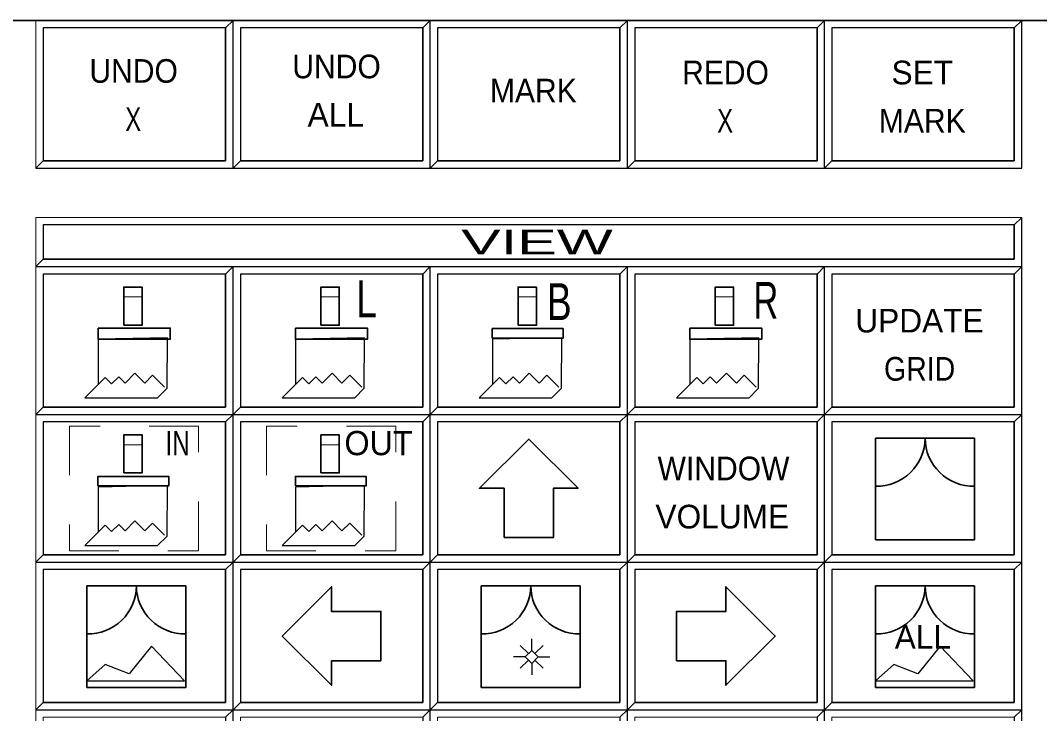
# Model space of a CAD drawing. Extents: x 95906.8 to 95923.6, y 90964.8 to 90972.8.
# Drawn here: x 95912.601 to 95914.669, y 90971.354 to 90972.762 of the extents above; entities that cross this region are included whole.
import ezdxf
from ezdxf.enums import TextEntityAlignment as Align

# ---------------------------------------------------------------- set-up
doc = ezdxf.new("R2010")
doc.units = 0
doc.header["$LTSCALE"] = 0.019
doc.linetypes.add('DOTTED', pattern=[1.5, 0.3, -1.2])
doc.linetypes.add('MEDIUM_DASHED', pattern=[4.5, 3, -1.5])
for name, color, linetype, lineweight in [('11', 7, 'Continuous', 25), ('12', 7, 'Continuous', 25), ('2', 7, 'Continuous', 13), ('21', 7, 'Continuous', 25), ('3', 7, 'Continuous', 25), ('6', 7, 'Continuous', 25), ('7', 7, 'Continuous', 35)]:
    doc.layers.add(name, color=color, linetype=linetype, lineweight=lineweight)

msp = doc.modelspace()

# ---------------------------------------------------------------- linework, layer by layer
at = {"layer": '11'}
for points in [[(95912.6473, 90972.4767), (95913.0173, 90972.4767), (95913.0173, 90972.7467), (95912.6473, 90972.7467)], [(95913.0473, 90972.4767), (95913.4173, 90972.4767), (95913.4173, 90972.7467), (95913.0473, 90972.7467)], [(95913.4473, 90972.4767), (95913.8173, 90972.4767), (95913.8173, 90972.7467), (95913.4473, 90972.7467)], [(95913.8473, 90972.4767), (95914.2173, 90972.4767), (95914.2173, 90972.7467), (95913.8473, 90972.7467)], [(95914.2473, 90972.4767), (95914.6173, 90972.4767), (95914.6173, 90972.7467), (95914.2473, 90972.7467)], [(95914.2473, 90971.9767), (95914.6173, 90971.9767), (95914.6173, 90972.2467), (95914.2473, 90972.2467)], [(95913.4473, 90971.6767), (95913.8173, 90971.6767), (95913.8173, 90971.9467), (95913.4473, 90971.9467)], [(95913.8473, 90971.6767), (95914.2173, 90971.6767), (95914.2173, 90971.9467), (95913.8473, 90971.9467)], [(95912.6473, 90971.3767), (95913.0173, 90971.3767), (95913.0173, 90971.6467), (95912.6473, 90971.6467)], [(95913.0473, 90971.3767), (95913.4173, 90971.3767), (95913.4173, 90971.6467), (95913.0473, 90971.6467)], [(95913.4473, 90971.3767), (95913.8173, 90971.3767), (95913.8173, 90971.6467), (95913.4473, 90971.6467)], [(95913.8473, 90971.3767), (95914.2173, 90971.3767), (95914.2173, 90971.6467), (95913.8473, 90971.6467)], [(95914.2473, 90971.3767), (95914.6173, 90971.3767), (95914.6173, 90971.6467), (95914.2473, 90971.6467)]]:
    msp.add_lwpolyline(points, close=True, dxfattribs=at)
at = {"layer": '12'}
for points in [[(95912.6473, 90971.9767), (95913.0173, 90971.9767), (95913.0173, 90972.2467), (95912.6473, 90972.2467)], [(95913.0473, 90971.9767), (95913.4173, 90971.9767), (95913.4173, 90972.2467), (95913.0473, 90972.2467)], [(95913.4473, 90971.9767), (95913.8173, 90971.9767), (95913.8173, 90972.2467), (95913.4473, 90972.2467)], [(95913.8473, 90971.9767), (95914.2173, 90971.9767), (95914.2173, 90972.2467), (95913.8473, 90972.2467)], [(95912.6473, 90971.6767), (95913.0173, 90971.6767), (95913.0173, 90971.9467), (95912.6473, 90971.9467)], [(95913.0473, 90971.6767), (95913.4173, 90971.6767), (95913.4173, 90971.9467), (95913.0473, 90971.9467)], [(95914.2473, 90971.6767), (95914.6173, 90971.6767), (95914.6173, 90971.9467), (95914.2473, 90971.9467)]]:
    msp.add_lwpolyline(points, close=True, dxfattribs=at)
at = {"layer": '2'}
for points in [[(95912.6323, 90972.7617), (95912.6323, 90972.4617), (95912.6473, 90972.4767), (95912.6473, 90972.7467), (95913.0173, 90972.7467), (95913.0323, 90972.7617)], [(95913.0323, 90972.7617), (95913.0323, 90972.4617), (95913.0473, 90972.4767), (95913.0473, 90972.7467), (95913.4173, 90972.7467), (95913.4323, 90972.7617)], [(95913.4323, 90972.7617), (95913.4323, 90972.4617), (95913.4473, 90972.4767), (95913.4473, 90972.7467), (95913.8173, 90972.7467), (95913.8323, 90972.7617)], [(95913.8323, 90972.7617), (95913.8323, 90972.4617), (95913.8473, 90972.4767), (95913.8473, 90972.7467), (95914.2173, 90972.7467), (95914.2323, 90972.7617)], [(95914.2323, 90972.7617), (95914.2323, 90972.4617), (95914.2473, 90972.4767), (95914.2473, 90972.7467), (95914.6173, 90972.7467), (95914.6323, 90972.7617)], [(95912.6323, 90972.3617), (95912.6323, 90972.2617), (95912.6473, 90972.2767), (95912.6473, 90972.3467), (95914.6173, 90972.3467), (95914.6323, 90972.3617)], [(95912.6323, 90972.2617), (95912.6323, 90971.9617), (95912.6473, 90971.9767), (95912.6473, 90972.2467), (95913.0173, 90972.2467), (95913.0323, 90972.2617)], [(95913.0323, 90972.2617), (95913.0323, 90971.9617), (95913.0473, 90971.9767), (95913.0473, 90972.2467), (95913.4173, 90972.2467), (95913.4323, 90972.2617)], [(95913.4323, 90972.2617), (95913.4323, 90971.9617), (95913.4473, 90971.9767), (95913.4473, 90972.2467), (95913.8173, 90972.2467), (95913.8323, 90972.2617)], [(95913.8323, 90972.2617), (95913.8323, 90971.9617), (95913.8473, 90971.9767), (95913.8473, 90972.2467), (95914.2173, 90972.2467), (95914.2323, 90972.2617)], [(95914.2323, 90972.2617), (95914.2323, 90971.9617), (95914.2473, 90971.9767), (95914.2473, 90972.2467), (95914.6173, 90972.2467), (95914.6323, 90972.2617)], [(95912.6323, 90971.9617), (95912.6323, 90971.6617), (95912.6473, 90971.6767), (95912.6473, 90971.9467), (95913.0173, 90971.9467), (95913.0323, 90971.9617)], [(95913.0323, 90971.9617), (95913.0323, 90971.6617), (95913.0473, 90971.6767), (95913.0473, 90971.9467), (95913.4173, 90971.9467), (95913.4323, 90971.9617)], [(95913.4323, 90971.9617), (95913.4323, 90971.6617), (95913.4473, 90971.6767), (95913.4473, 90971.9467), (95913.8173, 90971.9467), (95913.8323, 90971.9617)], [(95913.8323, 90971.9617), (95913.8323, 90971.6617), (95913.8473, 90971.6767), (95913.8473, 90971.9467), (95914.2173, 90971.9467), (95914.2323, 90971.9617)], [(95914.2323, 90971.9617), (95914.2323, 90971.6617), (95914.2473, 90971.6767), (95914.2473, 90971.9467), (95914.6173, 90971.9467), (95914.6323, 90971.9617)], [(95912.6323, 90971.6617), (95912.6323, 90971.3617), (95912.6473, 90971.3767), (95912.6473, 90971.6467), (95913.0173, 90971.6467), (95913.0323, 90971.6617)], [(95913.0323, 90971.6617), (95913.0323, 90971.3617), (95913.0473, 90971.3767), (95913.0473, 90971.6467), (95913.4173, 90971.6467), (95913.4323, 90971.6617)], [(95913.4323, 90971.6617), (95913.4323, 90971.3617), (95913.4473, 90971.3767), (95913.4473, 90971.6467), (95913.8173, 90971.6467), (95913.8323, 90971.6617)], [(95913.8323, 90971.6617), (95913.8323, 90971.3617), (95913.8473, 90971.3767), (95913.8473, 90971.6467), (95914.2173, 90971.6467), (95914.2323, 90971.6617)], [(95914.2323, 90971.6617), (95914.2323, 90971.3617), (95914.2473, 90971.3767), (95914.2473, 90971.6467), (95914.6173, 90971.6467), (95914.6323, 90971.6617)], [(95912.6323, 90971.3617), (95912.6323, 90971.0617), (95912.6473, 90971.0767), (95912.6473, 90971.3467), (95913.0173, 90971.3467), (95913.0323, 90971.3617)], [(95913.0323, 90971.3617), (95913.0323, 90971.0617), (95913.0473, 90971.0767), (95913.0473, 90971.3467), (95913.4173, 90971.3467), (95913.4323, 90971.3617)], [(95913.4323, 90971.3617), (95913.4323, 90971.0617), (95913.4473, 90971.0767), (95913.4473, 90971.3467), (95913.8173, 90971.3467), (95913.8323, 90971.3617)], [(95913.8323, 90971.3617), (95913.8323, 90971.0617), (95913.8473, 90971.0767), (95913.8473, 90971.3467), (95914.2173, 90971.3467), (95914.2323, 90971.3617)], [(95914.2323, 90971.3617), (95914.2323, 90971.0617), (95914.2473, 90971.0767), (95914.2473, 90971.3467), (95914.6173, 90971.3467), (95914.6323, 90971.3617)]]:
    msp.add_lwpolyline(points, close=True, dxfattribs=at)
at = {"layer": '21'}
msp.add_lwpolyline([(95912.6473, 90972.2767), (95914.6173, 90972.2767), (95914.6173, 90972.3467), (95912.6473, 90972.3467)], close=True, dxfattribs=at)
at = {"layer": '3'}
for points in [[(95912.6323, 90972.4617), (95913.0323, 90972.4617), (95913.0323, 90972.7617), (95913.0173, 90972.7467), (95913.0173, 90972.4767), (95912.6473, 90972.4767)], [(95913.0323, 90972.4617), (95913.4323, 90972.4617), (95913.4323, 90972.7617), (95913.4173, 90972.7467), (95913.4173, 90972.4767), (95913.0473, 90972.4767)], [(95913.4323, 90972.4617), (95913.8323, 90972.4617), (95913.8323, 90972.7617), (95913.8173, 90972.7467), (95913.8173, 90972.4767), (95913.4473, 90972.4767)], [(95913.8323, 90972.4617), (95914.2323, 90972.4617), (95914.2323, 90972.7617), (95914.2173, 90972.7467), (95914.2173, 90972.4767), (95913.8473, 90972.4767)], [(95914.2323, 90972.4617), (95914.6323, 90972.4617), (95914.6323, 90972.7617), (95914.6173, 90972.7467), (95914.6173, 90972.4767), (95914.2473, 90972.4767)], [(95912.6323, 90972.2617), (95914.6323, 90972.2617), (95914.6323, 90972.3617), (95914.6173, 90972.3467), (95914.6173, 90972.2767), (95912.6473, 90972.2767)], [(95912.6323, 90971.9617), (95913.0323, 90971.9617), (95913.0323, 90972.2617), (95913.0173, 90972.2467), (95913.0173, 90971.9767), (95912.6473, 90971.9767)], [(95913.0323, 90971.9617), (95913.4323, 90971.9617), (95913.4323, 90972.2617), (95913.4173, 90972.2467), (95913.4173, 90971.9767), (95913.0473, 90971.9767)], [(95913.4323, 90971.9617), (95913.8323, 90971.9617), (95913.8323, 90972.2617), (95913.8173, 90972.2467), (95913.8173, 90971.9767), (95913.4473, 90971.9767)], [(95913.8323, 90971.9617), (95914.2323, 90971.9617), (95914.2323, 90972.2617), (95914.2173, 90972.2467), (95914.2173, 90971.9767), (95913.8473, 90971.9767)], [(95914.2323, 90971.9617), (95914.6323, 90971.9617), (95914.6323, 90972.2617), (95914.6173, 90972.2467), (95914.6173, 90971.9767), (95914.2473, 90971.9767)], [(95912.6323, 90971.6617), (95913.0323, 90971.6617), (95913.0323, 90971.9617), (95913.0173, 90971.9467), (95913.0173, 90971.6767), (95912.6473, 90971.6767)], [(95913.0323, 90971.6617), (95913.4323, 90971.6617), (95913.4323, 90971.9617), (95913.4173, 90971.9467), (95913.4173, 90971.6767), (95913.0473, 90971.6767)], [(95913.4323, 90971.6617), (95913.8323, 90971.6617), (95913.8323, 90971.9617), (95913.8173, 90971.9467), (95913.8173, 90971.6767), (95913.4473, 90971.6767)], [(95913.8323, 90971.6617), (95914.2323, 90971.6617), (95914.2323, 90971.9617), (95914.2173, 90971.9467), (95914.2173, 90971.6767), (95913.8473, 90971.6767)], [(95914.2323, 90971.6617), (95914.6323, 90971.6617), (95914.6323, 90971.9617), (95914.6173, 90971.9467), (95914.6173, 90971.6767), (95914.2473, 90971.6767)], [(95912.6323, 90971.3617), (95913.0323, 90971.3617), (95913.0323, 90971.6617), (95913.0173, 90971.6467), (95913.0173, 90971.3767), (95912.6473, 90971.3767)], [(95913.0323, 90971.3617), (95913.4323, 90971.3617), (95913.4323, 90971.6617), (95913.4173, 90971.6467), (95913.4173, 90971.3767), (95913.0473, 90971.3767)], [(95913.4323, 90971.3617), (95913.8323, 90971.3617), (95913.8323, 90971.6617), (95913.8173, 90971.6467), (95913.8173, 90971.3767), (95913.4473, 90971.3767)], [(95913.8323, 90971.3617), (95914.2323, 90971.3617), (95914.2323, 90971.6617), (95914.2173, 90971.6467), (95914.2173, 90971.3767), (95913.8473, 90971.3767)], [(95914.2323, 90971.3617), (95914.6323, 90971.3617), (95914.6323, 90971.6617), (95914.6173, 90971.6467), (95914.6173, 90971.3767), (95914.2473, 90971.3767)], [(95912.6323, 90971.0617), (95913.0323, 90971.0617), (95913.0323, 90971.3617), (95913.0173, 90971.3467), (95913.0173, 90971.0767), (95912.6473, 90971.0767)], [(95913.0323, 90971.0617), (95913.4323, 90971.0617), (95913.4323, 90971.3617), (95913.4173, 90971.3467), (95913.4173, 90971.0767), (95913.0473, 90971.0767)], [(95913.4323, 90971.0617), (95913.8323, 90971.0617), (95913.8323, 90971.3617), (95913.8173, 90971.3467), (95913.8173, 90971.0767), (95913.4473, 90971.0767)], [(95913.8323, 90971.0617), (95914.2323, 90971.0617), (95914.2323, 90971.3617), (95914.2173, 90971.3467), (95914.2173, 90971.0767), (95913.8473, 90971.0767)], [(95914.2323, 90971.0617), (95914.6323, 90971.0617), (95914.6323, 90971.3617), (95914.6173, 90971.3467), (95914.6173, 90971.0767), (95914.2473, 90971.0767)]]:
    msp.add_lwpolyline(points, close=True, dxfattribs=at)
at = {"layer": '6', "linetype": 'MEDIUM_DASHED', "lineweight": 13}
for p, q in [((95913.6317, 90971.476), (95913.6151, 90971.4926)), ((95913.6317, 90971.476), (95913.6151, 90971.4926)), ((95913.6449, 90971.476), (95913.6615, 90971.4926)), ((95913.6449, 90971.476), (95913.6615, 90971.4926)), ((95913.6317, 90971.4628), (95913.6151, 90971.4463)), ((95913.6317, 90971.4628), (95913.6151, 90971.4463)), ((95913.6449, 90971.4628), (95913.6615, 90971.4463)), ((95913.6449, 90971.4628), (95913.6615, 90971.4463))]:
    msp.add_line(p, q, dxfattribs=at)
at = {"layer": '6'}
for p, q in [((95913.6383, 90971.4827), (95913.6383, 90971.5061)), ((95913.6383, 90971.4827), (95913.6383, 90971.5061)), ((95913.6251, 90971.4694), (95913.6016, 90971.4694)), ((95913.6383, 90971.4562), (95913.6383, 90971.4328)), ((95913.6383, 90971.4562), (95913.6383, 90971.4328)), ((95913.6515, 90971.4694), (95913.6749, 90971.4694)), ((95913.6515, 90971.4694), (95913.6749, 90971.4694))]:
    msp.add_line(p, q, dxfattribs=at)
at = {"layer": '6', "lineweight": 35}
for points in [[(95912.8105, 90972.1428), (95912.8477, 90972.1428), (95912.8477, 90972.2202), (95912.8105, 90972.2202)], [(95913.2105, 90972.1428), (95913.2477, 90972.1428), (95913.2477, 90972.2202), (95913.2105, 90972.2202)], [(95913.6105, 90972.1428), (95913.6477, 90972.1428), (95913.6477, 90972.2202), (95913.6105, 90972.2202)], [(95914.0105, 90972.1428), (95914.0477, 90972.1428), (95914.0477, 90972.2202), (95914.0105, 90972.2202)], [(95912.7589, 90972.1371), (95912.905, 90972.1371), (95912.905, 90972.1142), (95912.7589, 90972.1142)], [(95913.1589, 90972.1371), (95913.305, 90972.1371), (95913.305, 90972.1142), (95913.1589, 90972.1142)], [(95913.5582, 90972.1166), (95913.7018, 90972.1166), (95913.7018, 90972.1359), (95913.5582, 90972.1359)], [(95913.9589, 90972.1371), (95914.105, 90972.1371), (95914.105, 90972.1142), (95913.9589, 90972.1142)], [(95912.8105, 90971.8428), (95912.8477, 90971.8428), (95912.8477, 90971.9202), (95912.8105, 90971.9202)], [(95913.2105, 90971.8428), (95913.2477, 90971.8428), (95913.2477, 90971.9202), (95913.2105, 90971.9202)], [(95913.5823, 90971.7117), (95913.5823, 90971.8117), (95913.5323, 90971.8117), (95913.6323, 90971.9117), (95913.7323, 90971.8117), (95913.6823, 90971.8117), (95913.6823, 90971.7117)], [(95914.336, 90971.7072), (95914.5365, 90971.7072), (95914.5365, 90971.9134), (95914.336, 90971.9134)], [(95912.7584, 90971.8165), (95912.902, 90971.8165), (95912.902, 90971.8358), (95912.7584, 90971.8358)], [(95913.1588, 90971.8165), (95913.3024, 90971.8165), (95913.3024, 90971.8358), (95913.1588, 90971.8358)], [(95912.736, 90971.4072), (95912.9365, 90971.4072), (95912.9365, 90971.6134), (95912.736, 90971.6134)], [(95913.3323, 90971.4617), (95913.2323, 90971.4617), (95913.2323, 90971.4117), (95913.1323, 90971.5117), (95913.2323, 90971.6117), (95913.2323, 90971.5617), (95913.3323, 90971.5617)], [(95913.536, 90971.4072), (95913.7365, 90971.4072), (95913.7365, 90971.6134), (95913.536, 90971.6134)], [(95913.9323, 90971.4617), (95914.0323, 90971.4617), (95914.0323, 90971.4117), (95914.1323, 90971.5117), (95914.0323, 90971.6117), (95914.0323, 90971.5617), (95913.9323, 90971.5617)], [(95914.336, 90971.4072), (95914.5365, 90971.4072), (95914.5365, 90971.6134), (95914.336, 90971.6134)]]:
    msp.add_lwpolyline(points, close=True, dxfattribs=at)
at = {"layer": '6', "lineweight": 13}
for points in [[(95912.8477, 90972.2202), (95912.8105, 90972.2202), (95912.8105, 90972.2001), (95912.8477, 90972.2001)], [(95913.2477, 90972.2202), (95913.2105, 90972.2202), (95913.2105, 90972.2001), (95913.2477, 90972.2001)], [(95913.6477, 90972.2202), (95913.6105, 90972.2202), (95913.6105, 90972.2001), (95913.6477, 90972.2001)], [(95914.0477, 90972.2202), (95914.0105, 90972.2202), (95914.0105, 90972.2001), (95914.0477, 90972.2001)], [(95912.8477, 90971.9202), (95912.8105, 90971.9202), (95912.8105, 90971.9001), (95912.8477, 90971.9001)], [(95913.2477, 90971.9202), (95913.2105, 90971.9202), (95913.2105, 90971.9001), (95913.2477, 90971.9001)], [(95913.6383, 90971.4562), (95913.6516, 90971.4695), (95913.6383, 90971.4827), (95913.625, 90971.4695)], [(95913.6383, 90971.4562), (95913.6516, 90971.4695), (95913.6383, 90971.4827), (95913.625, 90971.4695)]]:
    msp.add_lwpolyline(points, close=True, dxfattribs=at)
at = {"layer": '6'}
for points in [[(95912.7589, 90972.1142), (95912.7589, 90972.0225), (95912.7317, 90971.9953), (95912.8792, 90971.9953), (95912.8986, 90972.0147), (95912.8993, 90972.1171)], [(95913.1589, 90972.1142), (95913.1589, 90972.0225), (95913.1317, 90971.9953), (95913.2792, 90971.9953), (95913.2986, 90972.0147), (95913.2993, 90972.1171)], [(95913.5589, 90972.1142), (95913.5589, 90972.0225), (95913.5317, 90971.9953), (95913.6792, 90971.9953), (95913.6986, 90972.0147), (95913.6993, 90972.1171)], [(95913.9589, 90972.1142), (95913.9589, 90972.0225), (95913.9317, 90971.9953), (95914.0792, 90971.9953), (95914.0986, 90972.0147), (95914.0993, 90972.1171)], [(95912.7589, 90971.8142), (95912.7589, 90971.7225), (95912.7317, 90971.6953), (95912.8792, 90971.6953), (95912.8986, 90971.7147), (95912.8993, 90971.8171)], [(95913.1589, 90971.8142), (95913.1589, 90971.7225), (95913.1317, 90971.6953), (95913.2792, 90971.6953), (95913.2986, 90971.7147), (95913.2993, 90971.8171)], [(95912.7357, 90971.4207), (95912.9341, 90971.4207), (95912.8668, 90971.4909), (95912.8217, 90971.4351), (95912.773, 90971.4537)], [(95914.3357, 90971.4207), (95914.5341, 90971.4207), (95914.4668, 90971.4909), (95914.4217, 90971.4351), (95914.373, 90971.4537)]]:
    msp.add_lwpolyline(points, close=True, dxfattribs=at)
at = {"layer": '6', "lineweight": 13}
for points in [[(95912.7589, 90972.0225), (95912.7732, 90972.0368), (95912.7861, 90972.0239), (95912.8004, 90972.0382), (95912.8133, 90972.0253), (95912.8334, 90972.0454), (95912.8534, 90972.0254), (95912.8691, 90972.0411), (95912.8935, 90972.0167)], [(95913.1589, 90972.0225), (95913.1732, 90972.0368), (95913.1861, 90972.0239), (95913.2004, 90972.0382), (95913.2133, 90972.0253), (95913.2334, 90972.0454), (95913.2534, 90972.0254), (95913.2691, 90972.0411), (95913.2935, 90972.0167)], [(95913.5589, 90972.0225), (95913.5732, 90972.0368), (95913.5861, 90972.0239), (95913.6004, 90972.0382), (95913.6133, 90972.0253), (95913.6334, 90972.0454), (95913.6534, 90972.0254), (95913.6691, 90972.0411), (95913.6935, 90972.0167)], [(95913.9589, 90972.0225), (95913.9732, 90972.0368), (95913.9861, 90972.0239), (95914.0004, 90972.0382), (95914.0133, 90972.0253), (95914.0334, 90972.0454), (95914.0534, 90972.0254), (95914.0691, 90972.0411), (95914.0935, 90972.0167)], [(95912.7589, 90971.7225), (95912.7732, 90971.7368), (95912.7861, 90971.7239), (95912.8004, 90971.7382), (95912.8133, 90971.7253), (95912.8334, 90971.7454), (95912.8534, 90971.7254), (95912.8691, 90971.7411), (95912.8935, 90971.7167)], [(95913.1589, 90971.7225), (95913.1732, 90971.7368), (95913.1861, 90971.7239), (95913.2004, 90971.7382), (95913.2133, 90971.7253), (95913.2334, 90971.7454), (95913.2534, 90971.7254), (95913.2691, 90971.7411), (95913.2935, 90971.7167)]]:
    msp.add_lwpolyline(points, dxfattribs=at)
at = {"layer": '6', "linetype": 'DOTTED', "lineweight": 13}
for points in [[(95912.7004, 90971.6848), (95912.9625, 90971.6848), (95912.9625, 90971.9381), (95912.7004, 90971.9381)], [(95913.1004, 90971.6848), (95913.3625, 90971.6848), (95913.3625, 90971.9381), (95913.1004, 90971.9381)]]:
    msp.add_lwpolyline(points, close=True, dxfattribs=at)
at = {"layer": '6', "lineweight": 35}
for centre, start, end in [((95914.3383, 90971.914), 268.6755, 359.6437), ((95914.5343, 90971.914), 180.3563, 271.3245), ((95912.7383, 90971.614), 268.6755, 359.6437), ((95912.9343, 90971.614), 180.3563, 271.3245), ((95913.5383, 90971.614), 268.6755, 359.6437), ((95913.7343, 90971.614), 180.3563, 271.3245), ((95914.3383, 90971.614), 268.6755, 359.6437), ((95914.5343, 90971.614), 180.3563, 271.3245)]:
    msp.add_arc(centre, 0.098, start, end, dxfattribs=at)
at = {"layer": '7'}
msp.add_lwpolyline([(95906.8323, 90972.7617), (95918.8323, 90972.7617), (95918.8323, 90964.7617), (95906.8323, 90964.7617)], close=True, dxfattribs=at)

# ---------------------------------------------------------------- texts
at = {"layer": '21', "width": 1.8}
msp.add_text('          VIEW         ', height=0.04999, dxfattribs=at).set_placement((95913.6322, 90972.2867), align=Align.CENTER)
at = {"layer": '6'}
for s, height, width, p in [('UNDO', 0.048, 0.95, (95913.2423, 90972.6441)), ('UNDO', 0.048, 0.95, (95912.8307, 90972.635)), ('REDO', 0.048, 0.95, (95914.0314, 90972.6319)), ('MARK', 0.048, 0.95, (95913.6416, 90972.5951)), ('X', 0.048, 0.75, (95912.8299, 90972.537)), ('X', 0.048, 0.75, (95914.0306, 90972.5339)), ('MARK', 0.048, 0.95, (95914.4306, 90972.534)), ('L', 0.075, 0.75, (95913.303, 90972.1586)), ('B', 0.075, 0.75, (95913.6941, 90972.1531)), ('R', 0.075, 0.7, (95914.1132, 90972.1558)), ('GRID', 0.048, 0.9, (95914.4252, 90972.0302)), ('IN', 0.0491, 0.75, (95912.92, 90971.8789)), ('WINDOW', 0.048, 0.95, (95914.0274, 90971.828))]:
    msp.add_text(s, height=height, dxfattribs=dict(at, width=width)).set_placement(p, align=Align.CENTER)
for s, height, p in [('SET', 0.048, (95914.4306, 90972.6318)), ('ALL', 0.048, (95913.2407, 90972.5461)), ('UPDATE', 0.048, (95914.4249, 90972.128)), ('OUT', 0.0491, (95913.3276, 90971.8789)), ('VOLUME', 0.048, (95914.0249, 90971.7302)), ('ALL', 0.048, (95914.4318, 90971.4859))]:
    msp.add_text(s, height=height, dxfattribs=at).set_placement(p, align=Align.CENTER)

doc.saveas('drawing.dxf')
